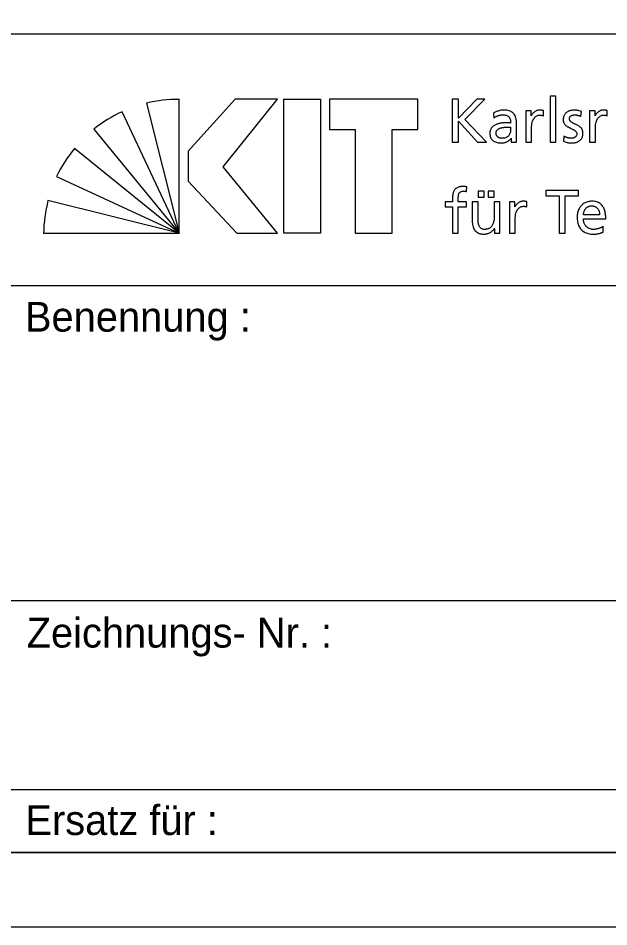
# Model space of a CAD drawing. Extents: x 0 to 14.9, y 0 to 10.5.
# Drawn here: x 12.641 to 13.633, y 0 to 1.526 of the extents above; entities that cross this region are included whole.
import ezdxf

# ---------------------------------------------------------------- set-up
doc = ezdxf.new("R2010")
doc.units = 0
doc.layers.add('90_Plankopf', color=7, linetype='Continuous')

msp = doc.modelspace()

# ---------------------------------------------------------------- linework, layer by layer
at = {"layer": '90_Plankopf'}
for p, q in [((10.278, 1.4998), (14.725, 1.4998)), ((10.278, 1.4998), (14.725, 1.4998)), ((12.912, 1.1647), (12.912, 1.3896)), ((13.3702, 1.3897), (13.3702, 1.3176)), ((12.8569, 1.3833), (12.912, 1.1647)), ((12.912, 1.1647), (12.8158, 1.3688)), ((13.4395, 1.3665), (13.44, 1.3583)), ((13.5232, 1.3621), (13.5232, 1.3708)), ((13.5864, 1.361), (13.5872, 1.3694)), ((13.6303, 1.3621), (13.6303, 1.3708)), ((13.478, 1.328), (13.478, 1.3497)), ((12.7686, 1.3396), (12.912, 1.1647)), ((13.4683, 1.3427), (13.4683, 1.3381)), ((13.5574, 1.328), (13.5569, 1.3193)), ((13.3702, 1.3176), (13.3806, 1.3176)), ((13.4126, 1.3176), (13.4277, 1.3176)), ((12.912, 1.1647), (12.7358, 1.3071)), ((12.706, 1.2603), (12.912, 1.1647)), ((13.3943, 1.2348), (13.3947, 1.2427)), ((12.912, 1.1647), (12.6914, 1.2197)), ((13.4957, 1.2091), (13.4957, 1.2178)), ((13.6177, 1.196), (13.5904, 1.196)), ((13.5904, 1.1888), (13.628, 1.1888)), ((13.6239, 1.1668), (13.6239, 1.1765)), ((12.6841, 1.1647), (12.912, 1.1647)), ((12.625, 1.0768), (14.725, 1.0768)), ((12.625, 0.548), (14.725, 0.548)), ((12.625, 0.2308), (14.725, 0.2308)), ((14.725, 0.125), (10.278, 0.125)), ((10.57, 0.125), (14.725, 0.125)), ((10.57, 0.125), (14.725, 0.125))]:
    msp.add_line(p, q, dxfattribs=at)
for points in [[(0, 0), (14.85, 0), (14.85, 10.5), (0, 10.5)], [(0.625, 10.375), (14.725, 10.375), (14.725, 0.125), (0.625, 0.125)], [(13.0767, 1.3897), (13.0059, 1.3897), (12.9268, 1.3025), (12.9268, 1.2523), (13.0084, 1.1647), (13.0771, 1.1647), (12.9856, 1.2766)], [(13.1493, 1.3897), (13.1493, 1.1647), (13.0875, 1.1647), (13.0875, 1.3897)], [(13.1641, 1.3897), (13.1641, 1.339), (13.2075, 1.339), (13.2075, 1.1647), (13.2693, 1.1647), (13.2693, 1.339), (13.3127, 1.339), (13.3127, 1.3897)]]:
    msp.add_lwpolyline(points, close=True, dxfattribs=at)
for points in [[(13.4277, 1.3176), (13.3912, 1.3556), (13.425, 1.3897), (13.4113, 1.3897), (13.3806, 1.358), (13.3806, 1.3897), (13.3702, 1.3897)], [(13.5345, 1.3176), (13.5442, 1.3176), (13.5442, 1.395), (13.5345, 1.395), (13.5345, 1.3176)], [(13.503, 1.3621), (13.5028, 1.3621), (13.5028, 1.3703), (13.4938, 1.3703), (13.4938, 1.3176), (13.5035, 1.3176), (13.5035, 1.3416)], [(13.6102, 1.3621), (13.61, 1.3621), (13.61, 1.3703), (13.6009, 1.3703), (13.6009, 1.3176), (13.6106, 1.3176), (13.6106, 1.3416)], [(13.3806, 1.3176), (13.3806, 1.3529), (13.4126, 1.3176)], [(13.4691, 1.3245), (13.4693, 1.3245), (13.4693, 1.3176), (13.4784, 1.3176)], [(13.5498, 1.1647), (13.5601, 1.1647), (13.5601, 1.2276), (13.5825, 1.2276), (13.5825, 1.2367), (13.5274, 1.2367), (13.5274, 1.2276), (13.5498, 1.2276), (13.5498, 1.1647)], [(13.3706, 1.2221), (13.3706, 1.2173), (13.3582, 1.2173), (13.3582, 1.2094), (13.3706, 1.2094), (13.3706, 1.1647), (13.3803, 1.1647), (13.3803, 1.2094), (13.3942, 1.2094), (13.3942, 1.2173), (13.3803, 1.2173), (13.3803, 1.223)], [(13.4139, 1.2356), (13.4139, 1.2253), (13.4236, 1.2253), (13.4236, 1.2356), (13.4139, 1.2356)], [(13.4308, 1.2356), (13.4308, 1.2253), (13.4405, 1.2253), (13.4405, 1.2356), (13.4308, 1.2356)], [(13.4135, 1.19), (13.4135, 1.2173), (13.4038, 1.2173), (13.4038, 1.186)], [(13.4504, 1.1647), (13.4504, 1.2173), (13.4407, 1.2173), (13.4407, 1.1929)], [(13.4756, 1.2091), (13.4754, 1.2091), (13.4754, 1.2173), (13.4663, 1.2173), (13.4663, 1.1647), (13.476, 1.1647), (13.476, 1.1886)], [(13.4408, 1.173), (13.441, 1.173), (13.441, 1.1647), (13.4504, 1.1647)]]:
    msp.add_lwpolyline(points, dxfattribs=at)
for centre, start, end in [((12.9112, 1.1514), 89.8053, 103.1895), ((12.9165, 1.1529), 115.0126, 128.3968), ((12.9204, 1.1566), 140.7898, 154.174), ((12.9223, 1.1609), 165.7222, 179.1064)]:
    msp.add_arc(centre, 0.2382, start, end, dxfattribs=at)
for points in [[(13.478, 1.3497), (13.478, 1.3545), (13.4773, 1.3585), (13.4758, 1.3617), (13.4744, 1.365), (13.4721, 1.3674), (13.469, 1.369), (13.4659, 1.3707), (13.4618, 1.3715), (13.4568, 1.3715), (13.4535, 1.3715), (13.4503, 1.371), (13.4474, 1.3701), (13.4445, 1.3692), (13.4419, 1.368), (13.4395, 1.3665)], [(13.44, 1.3583), (13.4413, 1.3594), (13.4428, 1.3604), (13.4445, 1.3611), (13.4461, 1.362), (13.4479, 1.3626), (13.4497, 1.363), (13.4516, 1.3634), (13.4534, 1.3637), (13.4553, 1.3637), (13.4585, 1.3637), (13.461, 1.3631), (13.4629, 1.3621), (13.4649, 1.3611), (13.4662, 1.3596), (13.467, 1.3575), (13.4679, 1.3555), (13.4683, 1.353), (13.4683, 1.3499)], [(13.5232, 1.3708), (13.5225, 1.3709), (13.5218, 1.371), (13.5212, 1.3712), (13.5206, 1.3713), (13.5199, 1.3713), (13.5192, 1.3714), (13.5185, 1.3715), (13.5177, 1.3715), (13.5168, 1.3715), (13.5149, 1.3715), (13.5131, 1.3711), (13.5113, 1.3703), (13.5095, 1.3695), (13.5079, 1.3684), (13.5065, 1.367), (13.5051, 1.3656), (13.5039, 1.3639), (13.503, 1.3621)], [(13.5035, 1.3416), (13.5035, 1.346), (13.5041, 1.3498), (13.5052, 1.353), (13.5064, 1.3562), (13.5081, 1.3587), (13.5102, 1.3604), (13.5124, 1.3621), (13.5149, 1.363), (13.5178, 1.363), (13.5186, 1.3631), (13.5195, 1.363), (13.5204, 1.3629), (13.5214, 1.3627), (13.5223, 1.3625), (13.5232, 1.3621)], [(13.5872, 1.3694), (13.5854, 1.37), (13.5834, 1.3705), (13.5815, 1.3709), (13.5795, 1.3713), (13.5774, 1.3715), (13.5752, 1.3715), (13.5726, 1.3715), (13.5701, 1.3712), (13.5679, 1.3705), (13.5656, 1.3698), (13.5637, 1.3688), (13.562, 1.3675), (13.5603, 1.3662), (13.559, 1.3645), (13.558, 1.3625), (13.5571, 1.3604), (13.5566, 1.358), (13.5566, 1.3553), (13.5566, 1.3532), (13.5571, 1.3514), (13.5579, 1.3498), (13.5587, 1.3483), (13.5598, 1.347), (13.5611, 1.3459), (13.5625, 1.3447), (13.564, 1.3437), (13.5656, 1.3429), (13.5672, 1.342), (13.5688, 1.3412), (13.5704, 1.3404), (13.5721, 1.3397), (13.5735, 1.3389), (13.5749, 1.338), (13.5762, 1.3373), (13.5773, 1.3363), (13.5782, 1.3353), (13.579, 1.3343), (13.5794, 1.3331), (13.5794, 1.3318), (13.5794, 1.3304), (13.5791, 1.3292), (13.5785, 1.3282), (13.5779, 1.3272), (13.5771, 1.3265), (13.5761, 1.3259), (13.5751, 1.3253), (13.5741, 1.3249), (13.5729, 1.3246), (13.5718, 1.3244), (13.5706, 1.3242), (13.5695, 1.3242), (13.5685, 1.3242), (13.5674, 1.3244), (13.566, 1.3247), (13.5646, 1.3249), (13.5631, 1.3253), (13.5616, 1.3259), (13.5601, 1.3265), (13.5587, 1.3271), (13.5574, 1.328)], [(13.5569, 1.3193), (13.5592, 1.3181), (13.5615, 1.3174), (13.5639, 1.317), (13.5664, 1.3166), (13.5689, 1.3164), (13.5714, 1.3164), (13.5737, 1.3164), (13.576, 1.3167), (13.5782, 1.3174), (13.5804, 1.318), (13.5823, 1.3191), (13.5841, 1.3204), (13.5858, 1.3217), (13.5872, 1.3234), (13.5882, 1.3255), (13.5892, 1.3276), (13.5897, 1.33), (13.5897, 1.3328), (13.5897, 1.3352), (13.5893, 1.3372), (13.5885, 1.3389), (13.5876, 1.3406), (13.5866, 1.342), (13.5852, 1.3431), (13.5839, 1.3443), (13.5824, 1.3453), (13.5807, 1.3461), (13.5791, 1.3469), (13.5775, 1.3477), (13.5759, 1.3484), (13.5743, 1.3491), (13.5728, 1.3499), (13.5714, 1.3507), (13.5701, 1.3515), (13.569, 1.3524), (13.5682, 1.3534), (13.5674, 1.3545), (13.5669, 1.3557), (13.5669, 1.3573), (13.5669, 1.3587), (13.5674, 1.3599), (13.5682, 1.3609), (13.5691, 1.3618), (13.5702, 1.3625), (13.5716, 1.363), (13.573, 1.3634), (13.5745, 1.3637), (13.5762, 1.3637), (13.5768, 1.3637), (13.5776, 1.3636), (13.5785, 1.3634), (13.5794, 1.3633), (13.5803, 1.3631), (13.5814, 1.3628), (13.5824, 1.3626), (13.5833, 1.3623), (13.5842, 1.362), (13.5851, 1.3616), (13.5859, 1.3613), (13.5864, 1.361)], [(13.6303, 1.3708), (13.6296, 1.3709), (13.629, 1.371), (13.6284, 1.3712), (13.6277, 1.3713), (13.6271, 1.3713), (13.6264, 1.3714), (13.6257, 1.3715), (13.6248, 1.3715), (13.6239, 1.3715), (13.622, 1.3715), (13.6202, 1.3711), (13.6184, 1.3703), (13.6167, 1.3695), (13.6151, 1.3684), (13.6136, 1.367), (13.6122, 1.3656), (13.611, 1.3639), (13.6102, 1.3621)], [(13.6106, 1.3416), (13.6106, 1.346), (13.6112, 1.3498), (13.6124, 1.353), (13.6136, 1.3562), (13.6152, 1.3587), (13.6173, 1.3604), (13.6195, 1.3621), (13.622, 1.363), (13.6249, 1.363), (13.6258, 1.3631), (13.6266, 1.363), (13.6276, 1.3629), (13.6285, 1.3627), (13.6294, 1.3625), (13.6303, 1.3621)], [(13.4683, 1.3499), (13.467, 1.35), (13.4658, 1.3501), (13.4647, 1.3501), (13.4636, 1.3501), (13.4626, 1.3501), (13.4615, 1.3501), (13.4604, 1.3501), (13.4592, 1.3501), (13.4579, 1.3501), (13.4559, 1.3501), (13.4538, 1.35), (13.4516, 1.3496), (13.4493, 1.3492), (13.4471, 1.3487), (13.445, 1.3478), (13.4429, 1.347), (13.441, 1.346), (13.4392, 1.3446), (13.4375, 1.3433), (13.4361, 1.3416), (13.4351, 1.3397), (13.434, 1.3377), (13.4335, 1.3354), (13.4335, 1.3328), (13.4335, 1.329), (13.4344, 1.3259), (13.436, 1.3235), (13.4376, 1.3211), (13.4399, 1.3193), (13.4427, 1.3181), (13.4456, 1.317), (13.449, 1.3164), (13.4528, 1.3164), (13.455, 1.3164), (13.457, 1.3167), (13.4588, 1.3172), (13.4605, 1.3177), (13.4621, 1.3184), (13.4634, 1.3192), (13.4648, 1.32), (13.4659, 1.3209), (13.4668, 1.3218), (13.4678, 1.3228), (13.4685, 1.3236), (13.4691, 1.3245)], [(13.4683, 1.3381), (13.4683, 1.3354), (13.4677, 1.3331), (13.4666, 1.331), (13.4655, 1.3289), (13.4638, 1.3273), (13.4617, 1.3261), (13.4595, 1.3249), (13.4568, 1.3243), (13.4536, 1.3242), (13.4525, 1.3242), (13.4514, 1.3244), (13.4502, 1.3248), (13.4491, 1.3252), (13.448, 1.3257), (13.447, 1.3264), (13.4461, 1.3272), (13.4453, 1.3281), (13.4447, 1.3291), (13.4441, 1.3302), (13.4438, 1.3314), (13.4438, 1.3328), (13.4438, 1.3347), (13.4443, 1.3362), (13.4452, 1.3374), (13.4461, 1.3387), (13.4473, 1.3396), (13.4487, 1.3404), (13.4502, 1.3411), (13.4517, 1.3417), (13.4534, 1.342), (13.455, 1.3424), (13.4566, 1.3426), (13.4582, 1.3428), (13.4597, 1.3429), (13.461, 1.3429), (13.4621, 1.3429), (13.4631, 1.3429), (13.4641, 1.3429), (13.4652, 1.3428), (13.4662, 1.3428), (13.4672, 1.3427), (13.4683, 1.3427)], [(13.4784, 1.3176), (13.4783, 1.3181), (13.4782, 1.3188), (13.4782, 1.3197), (13.4781, 1.3205), (13.4781, 1.3216), (13.478, 1.323), (13.478, 1.3243), (13.478, 1.326), (13.478, 1.328)], [(13.3947, 1.2427), (13.3938, 1.2428), (13.3928, 1.243), (13.3917, 1.2431), (13.3906, 1.2432), (13.3895, 1.2433), (13.3882, 1.2433), (13.3847, 1.2433), (13.3818, 1.2428), (13.3794, 1.2418), (13.3771, 1.2408), (13.3753, 1.2394), (13.3741, 1.2375), (13.3728, 1.2356), (13.3719, 1.2334), (13.3714, 1.2308), (13.3708, 1.2282), (13.3706, 1.2253), (13.3706, 1.2221)], [(13.3803, 1.223), (13.3803, 1.2247), (13.3804, 1.2264), (13.3806, 1.2279), (13.3808, 1.2294), (13.3812, 1.2307), (13.3819, 1.2319), (13.3825, 1.233), (13.3835, 1.2339), (13.3847, 1.2345), (13.386, 1.2351), (13.3876, 1.2354), (13.3897, 1.2354), (13.3905, 1.2354), (13.3914, 1.2354), (13.3922, 1.2353), (13.393, 1.2352), (13.3938, 1.235), (13.3943, 1.2348)], [(13.4957, 1.2178), (13.495, 1.2179), (13.4943, 1.2181), (13.4938, 1.2182), (13.4931, 1.2183), (13.4925, 1.2184), (13.4917, 1.2184), (13.4911, 1.2185), (13.4902, 1.2185), (13.4893, 1.2185), (13.4874, 1.2185), (13.4856, 1.2181), (13.4838, 1.2173), (13.4821, 1.2165), (13.4805, 1.2154), (13.479, 1.214), (13.4776, 1.2126), (13.4764, 1.211), (13.4756, 1.2091)], [(13.476, 1.1886), (13.476, 1.193), (13.4766, 1.1968), (13.4778, 1.2), (13.4789, 1.2032), (13.4806, 1.2057), (13.4827, 1.2074), (13.4849, 1.2092), (13.4874, 1.21), (13.4903, 1.21), (13.4912, 1.2101), (13.492, 1.21), (13.493, 1.2099), (13.4939, 1.2097), (13.4948, 1.2095), (13.4957, 1.2091)], [(13.628, 1.1888), (13.628, 1.1931), (13.6276, 1.197), (13.6268, 1.2006), (13.626, 1.2042), (13.6247, 1.2073), (13.6229, 1.21), (13.6211, 1.2127), (13.6188, 1.2148), (13.6158, 1.2162), (13.6128, 1.2177), (13.6091, 1.2185), (13.6047, 1.2185), (13.601, 1.2185), (13.5976, 1.2178), (13.5946, 1.2166), (13.5916, 1.2152), (13.589, 1.2134), (13.5868, 1.2111), (13.5847, 1.2087), (13.583, 1.2059), (13.5819, 1.2026), (13.5807, 1.1994), (13.5801, 1.1958), (13.5801, 1.1919), (13.5801, 1.1876), (13.5806, 1.1837), (13.5817, 1.1802), (13.5828, 1.1767), (13.5845, 1.1737), (13.5867, 1.1712), (13.5889, 1.1687), (13.5918, 1.1668), (13.5952, 1.1655), (13.5986, 1.1641), (13.6027, 1.1634), (13.6073, 1.1634), (13.6102, 1.1634), (13.6126, 1.1636), (13.6147, 1.164), (13.6167, 1.1644), (13.6184, 1.1648), (13.6199, 1.1653), (13.6214, 1.1659), (13.6227, 1.1664), (13.6239, 1.1668)], [(13.5904, 1.196), (13.5906, 1.1977), (13.591, 1.1995), (13.5916, 1.2012), (13.5922, 1.2029), (13.5931, 1.2045), (13.5942, 1.2059), (13.5953, 1.2073), (13.5967, 1.2085), (13.5984, 1.2093), (13.6001, 1.2102), (13.6022, 1.2107), (13.6045, 1.2107), (13.6066, 1.2107), (13.6085, 1.2103), (13.6101, 1.2095), (13.6117, 1.2088), (13.6131, 1.2077), (13.6142, 1.2064), (13.6153, 1.205), (13.6162, 1.2035), (13.6168, 1.2017), (13.6174, 1.1999), (13.6177, 1.1981), (13.6177, 1.196)], [(13.4407, 1.1929), (13.4407, 1.1897), (13.4404, 1.1868), (13.4397, 1.1841), (13.4391, 1.1815), (13.4381, 1.1792), (13.4368, 1.1773), (13.4355, 1.1754), (13.4338, 1.1739), (13.4318, 1.1728), (13.4298, 1.1718), (13.4274, 1.1713), (13.4247, 1.1713), (13.4219, 1.1714), (13.4197, 1.1722), (13.418, 1.1736), (13.4164, 1.175), (13.4152, 1.1771), (13.4145, 1.1798), (13.4139, 1.1825), (13.4135, 1.1859), (13.4135, 1.19)], [(13.4038, 1.186), (13.4038, 1.1813), (13.4045, 1.1772), (13.4059, 1.1739), (13.4073, 1.1705), (13.4095, 1.1679), (13.4124, 1.1661), (13.4153, 1.1644), (13.419, 1.1634), (13.4236, 1.1634), (13.426, 1.1634), (13.4284, 1.1638), (13.4306, 1.1646), (13.4329, 1.1653), (13.4349, 1.1665), (13.4367, 1.1679), (13.4384, 1.1693), (13.4398, 1.171), (13.4408, 1.173)], [(13.6239, 1.1765), (13.6233, 1.176), (13.6225, 1.1755), (13.6213, 1.1749), (13.6202, 1.1743), (13.6189, 1.1737), (13.6174, 1.1732), (13.6159, 1.1726), (13.6143, 1.1722), (13.6126, 1.1718), (13.611, 1.1715), (13.6094, 1.1713), (13.6077, 1.1713), (13.6054, 1.1713), (13.6032, 1.1717), (13.6012, 1.1725), (13.5991, 1.1734), (13.5972, 1.1746), (13.5956, 1.1761), (13.594, 1.1777), (13.5927, 1.1795), (13.5918, 1.1817), (13.5909, 1.1838), (13.5904, 1.1862), (13.5904, 1.1888)]]:
    msp.add_open_spline(points, degree=3, dxfattribs=at)

# ---------------------------------------------------------------- texts
for s, p in [('Benennung :', (12.6528, 0.9995)), ('Zeichnungs- Nr. :', (12.6557, 0.469)), ('Ersatz für :', (12.6535, 0.1542))]:
    msp.add_text(s, height=0.05, dxfattribs=at).set_placement(p)

doc.saveas('drawing.dxf')
